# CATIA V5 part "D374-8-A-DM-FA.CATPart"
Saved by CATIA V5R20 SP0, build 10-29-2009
Part number: D374-8-A-DM-FA
Bounding box of the stored display mesh (mm): x -10 to 0.25, y -4 to 4, z -4 to 4
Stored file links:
  C:\Users\Utente\Desktop\IO LAVORO\3D X SITO CF\X SITO\PLASTICA\D374\D374-8-A-DM-FA.CATPart
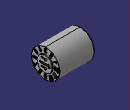
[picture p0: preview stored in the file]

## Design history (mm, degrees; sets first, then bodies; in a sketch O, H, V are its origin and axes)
Set1
  DatumSurface1 to DatumSurface222 "D374-8-A-DM-FA"
Body1 (main body)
